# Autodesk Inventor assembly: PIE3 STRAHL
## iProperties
Shininess: 64.0
Length Units: 11269
Angle Units: 11279
Time Units: 11290
Mass Units: 11286
Length Display Precision: 3
Angle Display Precision: 2
Compacted: True
Part Number: PIE3 STRAHL
Document SubType Name: Assembly
Created: 2004-08
Designer: John Blackburn
Manufacturer: Standard
Standards Organization: Custom
Density: 0.0
Volumn: 0.0
Area: 0.0
PropertySet Name: Model Information
Control State: 0
Master: False
Checked Out: False
Author: John Blackburn
